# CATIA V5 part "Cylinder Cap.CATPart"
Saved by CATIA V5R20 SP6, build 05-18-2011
Part number: Cylinder Cap
Bounding box of the stored display mesh (mm): x 0 to 41.75, y -28.992 to 28.992, z -53.343 to 53.343
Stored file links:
  E:\#00 CATIA V5 Movie\#03 CATIA V5 Data\#07 KIN\Balance Unit (1)\Cylinder Cap.CATPart
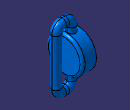
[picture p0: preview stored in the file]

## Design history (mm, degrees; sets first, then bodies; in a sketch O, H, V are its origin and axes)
Body1 (main body)
  Sketch1 on zx-plane, origin (0, 0, 0), H (-1, 0, 0), V (0, 0, 1)
    axis line L1 (0, 0) -> (-166.1003, 0)
    point P2 (0, 29)
    line L2 (0, 29) -> (-22, 29)
    line L3 (-22, 29) -> (-22, 0)
    point P4 (-22, 0)
    line L4 (0, 29) -> (0, 27)
    line L5 (0, 27) -> (-20, 27)
    line L6 (-20, 27) -> (-20, 0)
    point P7 (-20, 0)
    distance L5 L1 = 27
    distance L2 L5 = 2
    distance L6 L3 = 2
    distance V L6 = 20
    horizontal: L1 H, L2 H, L5 H
    coincidence: P2 V, P4 L1, P7 L1
    vertical: L3 V, L4 V, L6 V
  Shaft1: profile Sketch1, axis Sketch1.L1, angle 360
  Fillet1: radius 2, on edge [face of Shaft1 from Sketch1.L6 | face of Shaft1 from Sketch1.L5]
  Fillet2: radius 4, on face of Shaft1 from Sketch1.L3
  Body2
    Sketch2 on xy-plane, origin (0, 0, 0), H (1, 0, 0), V (0, 1, 0)
      circle A1 centre (35, 0) radius 6.75
      point P1 (35, 0)
      radius A1 = 6.75
      distance V P1 = 35
      coincidence: P1 H
    Sketch3 on zx-plane, origin (0, 0, 0), H (-1, 0, 0), V (0, 0, 1)
      point P1 (-35.4004, 0)
      line L1 (-35.4004, 0) -> (-35.4004, 36.9938)
      line L2 (-25.4004, 46.9938) -> (-20.561, 46.9938)
      line L3 (-10.561, 36.9938) -> (-10.561, 22.7864)
      arc A1 centre (-25.4004, 36.9938) radius 10 from (-35.4004, 36.9938) to (-25.4004, 46.9938) cw
      arc A2 centre (-20.561, 36.9938) radius 10 from (-20.561, 46.9938) to (-10.561, 36.9938) cw
      radius A1 = 10
      radius A2 = 10 {= Sketch3.radius(A1)}
      distance H L2 = 46.9938
      distance V L1 = 35.4004
      distance L3 V = 10.561
      coincidence: P1 H
      vertical: L1 V, L3 V
      horizontal: L2 H
      tangency: A1 L1, A1 L2, A2 L2, A2 L3
    Rib1: profile Sketch2, centre curve Sketch3
    Mirror1: of the body so far, about xy-plane
  Trim1: tool Body2, faces to remove face of Rib1; face of Mirror1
